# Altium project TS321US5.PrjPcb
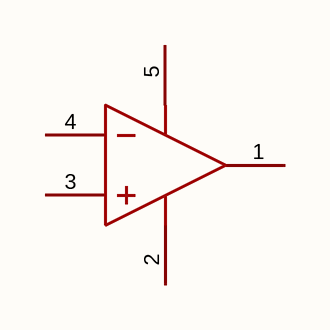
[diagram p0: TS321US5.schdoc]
1 sheet, 1 parts. Net scope: global (net labels, ports and power ports of the same name join across sheets).

## Sheet TS321US5.schdoc
size 127 x 101 mm

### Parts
U?  ts321us5  [SOT-23-5_L3.0-W1.7-P0.95-LS2.8-BR]  (value not drawn)

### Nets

Not connected (* = marked no-connect by the designer): U? 1(OUT) 2(VCC-) 3(IN+) 4(IN-) 5(VCC+)

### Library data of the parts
U? = ts321us5: 放大器数:-;轨到轨:-;增益带宽积(GBW):1MHz;输入失调电压(Vos):2mV;压摆率(SR):400V/ms;输入偏置电流(Ib):45nA;; Manufacturer: TECH PUBLIC(台舟); AddInBom: yes; ModelId: 0a2a1b8f50944f73965918ad6e5fe167; ModelName: SOT-23-5_L2.9-W1.6-H1.1-LS2.8-P0.95; ModelTransform: 114.173,109.636,0,180,0,0,0,0,0; Gain Bandwidth Product: 1MHz; Vos - Input Offset Voltage: 2mV; Ib - Input Bias Current: 45nA; Input Offset Current(Ios): 3nA; Common Mode Rejection Ratio(CMRR): 90dB; Quiescent Current: 100uA; Output Current: 40mA; Single supply: 3V~32V; Dual Supply: 1.5V~16V；-16V~-1.5V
